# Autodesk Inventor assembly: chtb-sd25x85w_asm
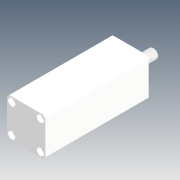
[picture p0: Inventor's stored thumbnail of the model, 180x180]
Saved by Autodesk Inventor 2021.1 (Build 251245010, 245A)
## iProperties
Company: Microsoft
Created: 2018-05
Part Number: chtb-sd25x85w_asm
Description: STEP AP214
Document SubType Name: Assembly
Designer: user
Title: chtb-sd25x85w_asm.STEP
Author: Windows
Revision Number: ÈÎºÎ
Sending System: SolidWorks 2015
Preprocessor: SwSTEP 2.0
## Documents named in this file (4)
- D:\Vault_2016\Projekty\Clamptek\Hydraulic\CHTB\CHTB-25\Inventor\chtb-sd25x85w\chtb-sd25x85w_asm.iam
- D:\Vault_2016\Projekty\Clamptek\Hydraulic\CHTB\CHTB-25\Inventor\chtb-sd25x85w\CHTB-25QG.ipt
- D:\Vault_2016\Projekty\Clamptek\Hydraulic\CHTB\CHTB-25\Inventor\chtb-sd25x85w\CHTB-SD25X85NBT.ipt
- D:\Vault_2016\Projekty\Clamptek\Hydraulic\CHTB\CHTB-25\Inventor\chtb-sd25x85w\CHTB-SD25X85WHSG.ipt
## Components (3 placed, 3 different names)
1. CHTB-25QG_1
2. CHTB-SD25X85NBT_2
3. CHTB-SD25X85WHSG_3
